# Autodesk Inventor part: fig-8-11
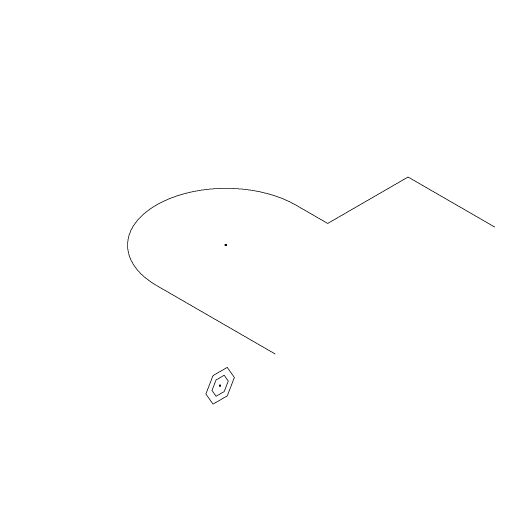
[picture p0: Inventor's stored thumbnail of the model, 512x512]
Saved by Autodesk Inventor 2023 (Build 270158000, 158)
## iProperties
Created: 2004-05
Part Number: fig-8-11
Document SubType Name: Modeling
Designer: CADCIM Technologies
Manufacturer: Standard
Standards Organization: Custom
Density: 1 g/cm^3
Material: Generic
Appearance: Default
Author: CADCIM Technologies
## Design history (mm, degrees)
sketch "Sketch1"
  geometry: L1 (-42.583, 3.219)-(-90.066, 3.219); L2 (-90.066, 58.92)-(-77.282, 58.92); L3 (-77.282, 58.92)-(-77.282, 91.063); L4 (-77.282, 91.063)-(-42.583, 91.063); A1 r 27.851 centre (-90.066, 31.07) between (-90.066, 58.92) and (-90.066, 3.219)
  constraints: 8 end point, 2 parallel, 2 point on circle, 2 tangent, 1 centre point, 1 perpendicular
workplane "Work Plane2"
body "Solid1"
sketch "Sketch2"
  geometry: L1 (16.303, 0)-(19.151, 4.934); L2 (19.151, 4.934)-(24.849, 4.934); L3 (24.849, 4.934)-(27.697, 0); L4 (27.697, 0)-(24.849, -4.934); L5 (24.849, -4.934)-(19.151, -4.934); L6 (19.151, -4.934)-(16.303, 0); L7 (18.744, 0)-(20.372, 2.819); L8 (20.372, 2.819)-(23.628, 2.819); L9 (23.628, 2.819)-(25.256, 0); L10 (25.256, 0)-(23.628, -2.819); L11 (23.628, -2.819)-(20.372, -2.819); L12 (20.372, -2.819)-(18.744, 0); 2 further points
  constraints: 24 end point, 1 coincident, 22 other
